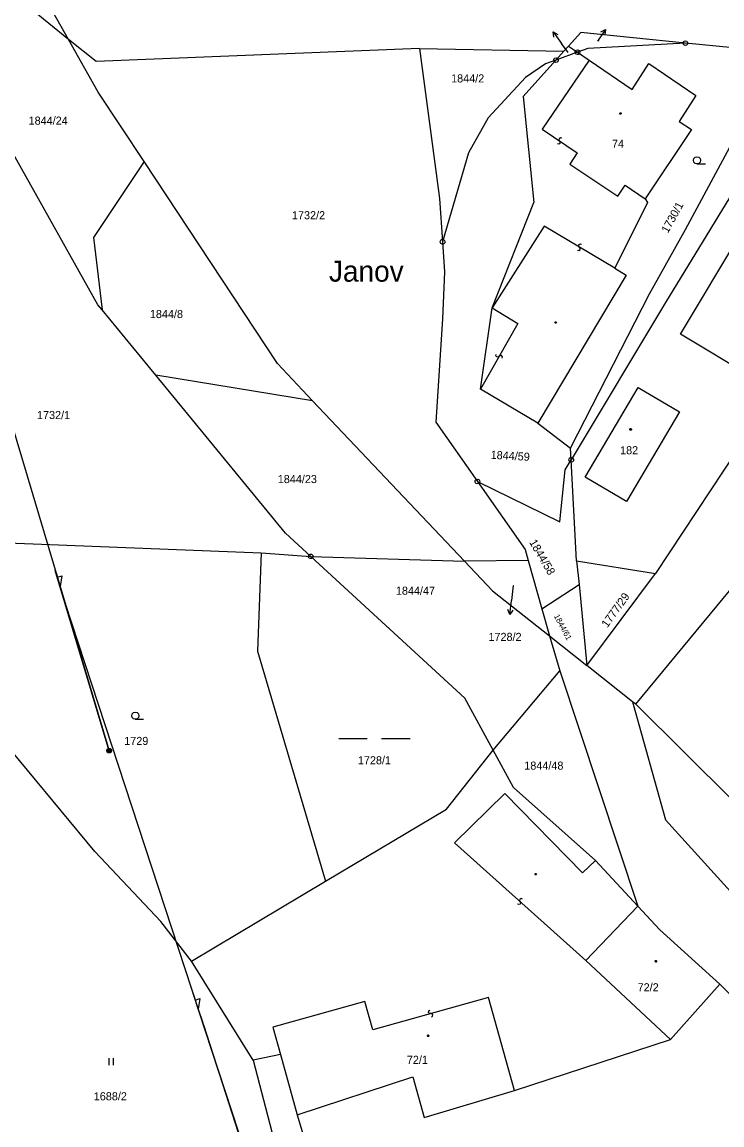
# Model space of a CAD drawing. Extents: x -747792 to -745414, y -1093712 to -1091463.
# Drawn here: x -747029.6 to -746956.1, y -1092274.2 to -1092158.4 of the extents above; entities that cross this region are included whole.
import ezdxf

# ---------------------------------------------------------------- set-up
doc = ezdxf.new("R2010")
doc.units = 0
for name, color, linetype in [('Pracovní_bod JDTM STC_VC', 7, 'Continuous'), ('Pracovní_bod JDTM STC_VC - výška', 7, 'Continuous'), ('Pracovní_bod JDTM STC_VC - číslo', 7, 'Continuous'), ('Pracovní_bod NN - výška', 7, 'Continuous'), ('Pracovní_bod polohopisu', 7, 'Continuous'), ('Pracovní_bod polohopisu - výška', 7, 'Continuous'), ('Pracovní_bod polohopisu - číslo', 7, 'Continuous'), ('Pracovní_bod VN - výška', 7, 'Continuous')]:
    doc.layers.add(name, color=color, linetype=linetype)

msp = doc.modelspace()

# ---------------------------------------------------------------- linework, layer by layer
at = {"layer": 'Pracovní_bod JDTM STC_VC - výška'}
for points in [[(-746966.77, -1092167.94), (-746966.72, -1092167.95), (-746966.7, -1092167.99), (-746966.69, -1092168.02), (-746966.7, -1092168.06), (-746966.74, -1092168.1), (-746966.77, -1092168.1), (-746966.82, -1092168.09), (-746966.84, -1092168.06), (-746966.85, -1092168.02), (-746966.84, -1092167.98), (-746966.8, -1092167.94)], [(-746973.52, -1092189.89), (-746973.47, -1092189.96), (-746973.52, -1092190.03), (-746973.6, -1092190.03), (-746973.65, -1092189.96), (-746973.6, -1092189.89)], [(-746965.68, -1092201.09), (-746965.63, -1092201.1), (-746965.6, -1092201.15), (-746965.59, -1092201.18), (-746965.6, -1092201.23), (-746965.65, -1092201.26), (-746965.68, -1092201.27), (-746965.73, -1092201.25), (-746965.76, -1092201.22), (-746965.77, -1092201.18), (-746965.76, -1092201.13), (-746965.72, -1092201.1)], [(-746975.6, -1092247.8), (-746975.56, -1092247.88), (-746975.6, -1092247.95), (-746975.7, -1092247.95), (-746975.74, -1092247.88), (-746975.7, -1092247.8)], [(-746963.05, -1092256.93), (-746963, -1092256.94), (-746962.98, -1092256.98), (-746962.97, -1092257.01), (-746962.98, -1092257.06), (-746963.02, -1092257.09), (-746963.05, -1092257.09), (-746963.09, -1092257.08), (-746963.12, -1092257.05), (-746963.14, -1092257.01), (-746963.12, -1092256.96), (-746963.08, -1092256.93)], [(-746986.95, -1092264.75), (-746986.9, -1092264.76), (-746986.88, -1092264.8), (-746986.86, -1092264.83), (-746986.88, -1092264.88), (-746986.92, -1092264.91), (-746986.95, -1092264.92), (-746986.99, -1092264.9), (-746987.02, -1092264.87), (-746987.03, -1092264.83), (-746987.02, -1092264.79), (-746986.98, -1092264.75)]]:
    msp.add_lwpolyline(points, close=True, dxfattribs=at)
at = {"layer": 'Pracovní_bod JDTM STC_VC - číslo'}
for points in [[(-746958.73, -1092173.31), (-746958.92, -1092173.26), (-746959.05, -1092173.12), (-746959.1, -1092172.94), (-746959.05, -1092172.75), (-746958.92, -1092172.61), (-746958.73, -1092172.56), (-746958.54, -1092172.61), (-746958.41, -1092172.75), (-746958.35, -1092172.94), (-746958.41, -1092173.12), (-746958.54, -1092173.26), (-746958.73, -1092173.31), (-746957.85, -1092173.31)], [(-747017.7, -1092231.61), (-747017.89, -1092231.56), (-747018.02, -1092231.42), (-747018.08, -1092231.24), (-747018.02, -1092231.05), (-747017.89, -1092230.91), (-747017.7, -1092230.86), (-747017.51, -1092230.91), (-747017.38, -1092231.05), (-747017.33, -1092231.24), (-747017.38, -1092231.42), (-747017.51, -1092231.56), (-747017.7, -1092231.61), (-747016.83, -1092231.61)], [(-746996.34, -1092233.64), (-746993.34, -1092233.64)], [(-746991.84, -1092233.64), (-746988.84, -1092233.64)], [(-747020.49, -1092267.17), (-747020.49, -1092267.92)], [(-747019.99, -1092267.92), (-747019.99, -1092267.17)]]:
    msp.add_lwpolyline(points, dxfattribs=at)
at = {"layer": 'Pracovní_bod NN - výška'}
for points in [[(-747024.71, -1092160.27), (-747034.1, -1092143.66)], [(-747024.71, -1092160.27), (-747037.12, -1092150.15)], [(-746970.91, -1092159.54), (-746972.2, -1092160.96)], [(-746959.95, -1092160.64), (-746970.91, -1092159.54)], [(-747021.59, -1092165.8), (-747024.71, -1092160.27)], [(-747021.82, -1092162.57), (-747024.71, -1092160.27)], [(-746945.49, -1092160), (-746948.23, -1092165.29), (-746962.05, -1092187.86), (-746971.93, -1092204.37)], [(-746959.95, -1092160.64), (-746970.19, -1092161.2)], [(-746949.91, -1092161.64), (-746959.95, -1092160.64)], [(-746987.85, -1092161.22), (-747021.82, -1092162.57)], [(-746987.85, -1092161.22), (-746985.75, -1092176.94)], [(-746987.85, -1092161.22), (-746972.69, -1092161.5)], [(-746973.53, -1092162.43), (-746972.69, -1092161.5)], [(-746971.28, -1092161.6), (-746973.53, -1092162.43)], [(-746972.2, -1092160.96), (-746972.69, -1092161.5)], [(-746972.2, -1092160.96), (-746971.28, -1092161.6)], [(-746970.19, -1092161.2), (-746971.28, -1092161.6)], [(-746971.28, -1092161.6), (-746970.06, -1092162.44)], [(-746959.95, -1092180.22), (-746949.91, -1092161.64)], [(-747021.62, -1092188.1), (-747035.75, -1092163)], [(-746976.98, -1092166.24), (-746973.53, -1092162.43)], [(-746974.63, -1092162.83), (-746976.74, -1092164.24)], [(-746973.53, -1092162.43), (-746974.63, -1092162.83)], [(-746970.06, -1092162.44), (-746965.52, -1092165.5)], [(-746965.52, -1092165.5), (-746963.79, -1092162.77)], [(-746963.79, -1092162.77), (-746958.85, -1092166.14)], [(-746976.74, -1092164.24), (-746980.64, -1092168.47)], [(-747016.78, -1092173.07), (-747021.59, -1092165.8)], [(-746976.98, -1092166.24), (-746975.87, -1092177.38)], [(-746958.85, -1092166.14), (-746960.61, -1092168.85)], [(-746980.64, -1092168.47), (-746982.72, -1092172.16)], [(-746959.32, -1092169.69), (-746964.15, -1092176.99)], [(-746960.61, -1092168.85), (-746959.32, -1092169.69)], [(-746982.72, -1092172.16), (-746985.44, -1092181.49)], [(-747016.78, -1092173.07), (-747022.1, -1092181.03)], [(-747002.78, -1092194.26), (-747016.78, -1092173.07)], [(-746985.75, -1092176.94), (-746985.44, -1092181.49)], [(-746980.24, -1092188.43), (-746975.87, -1092177.38)], [(-746963.93, -1092177.37), (-746967.35, -1092184.27)], [(-746964.15, -1092176.99), (-746963.93, -1092177.37)], [(-746963.7, -1092186.96), (-746959.95, -1092180.22)], [(-747022.1, -1092181.03), (-747021.19, -1092188.62)], [(-746985.44, -1092181.49), (-746985.23, -1092184.63)], [(-746960.47, -1092191.19), (-746954.11, -1092180.64)], [(-746985.23, -1092184.63), (-746985.44, -1092189.59)], [(-746966.15, -1092184.99), (-746975.42, -1092200.54)], [(-746967.35, -1092184.27), (-746966.15, -1092184.99)], [(-746971.99, -1092203.15), (-746963.7, -1092186.96)], [(-747021.19, -1092188.62), (-747021.62, -1092188.1)], [(-746981.44, -1092196.97), (-746980.24, -1092188.43)], [(-747015.55, -1092195.49), (-747021.19, -1092188.62)], [(-746985.44, -1092189.59), (-746986.15, -1092200.44)], [(-746952.49, -1092195.99), (-746960.47, -1092191.19)], [(-747002.78, -1092194.26), (-746999.08, -1092198.17)], [(-746999.08, -1092198.17), (-747015.55, -1092195.49)], [(-747001.92, -1092212.08), (-747015.55, -1092195.49)], [(-746975.42, -1092200.54), (-746981.44, -1092196.97)], [(-746970.46, -1092206.2), (-746964.91, -1092196.78)], [(-746964.91, -1092196.78), (-746960.58, -1092199.33)], [(-746950.17, -1092196.79), (-746963.07, -1092216.32)], [(-746999.08, -1092198.17), (-746983.14, -1092215.01)], [(-746960.58, -1092199.33), (-746966.13, -1092208.74)], [(-746986.15, -1092200.44), (-746981.78, -1092206.66)], [(-746975.42, -1092200.54), (-746971.99, -1092203.15)], [(-746971.93, -1092204.37), (-746971.99, -1092203.15)], [(-746972.56, -1092205.43), (-746971.93, -1092204.37)], [(-746971.36, -1092214.98), (-746971.93, -1092204.37)], [(-746965.16, -1092230.04), (-746943.99, -1092204.43)], [(-746973.12, -1092210.88), (-746972.56, -1092205.43)], [(-746981.78, -1092206.66), (-746973.12, -1092210.88)], [(-746981.78, -1092206.66), (-746976.77, -1092213.78)], [(-746966.13, -1092208.74), (-746970.46, -1092206.2)], [(-746999.28, -1092214.51), (-747001.92, -1092212.08)], [(-747037.36, -1092212.86), (-747004.48, -1092214.14)], [(-746976.77, -1092213.78), (-746976.44, -1092214.96)], [(-747004.48, -1092214.14), (-747004.88, -1092224.46)], [(-747004.48, -1092214.14), (-746999.28, -1092214.51)], [(-746999.28, -1092214.51), (-746983.14, -1092215.01)], [(-746983.11, -1092229.41), (-746999.28, -1092214.51)], [(-746976.44, -1092214.96), (-746983.14, -1092215.01)], [(-746983.14, -1092215.01), (-746980.19, -1092218.13)], [(-746976.44, -1092214.96), (-746975.01, -1092220.01)], [(-746971.36, -1092214.98), (-746963.07, -1092216.32)], [(-746971.36, -1092214.98), (-746971.11, -1092217.47)], [(-746970.28, -1092225.96), (-746963.07, -1092216.32)], [(-746980.19, -1092218.13), (-746974.21, -1092222.85)], [(-746975.01, -1092220.01), (-746971.11, -1092217.47)], [(-746971.11, -1092217.47), (-746970.28, -1092225.96)], [(-746975.01, -1092220.01), (-746974.21, -1092222.85)], [(-746974.21, -1092222.85), (-746973.13, -1092226.53)], [(-746974.21, -1092222.85), (-746970.28, -1092225.96)], [(-747004.88, -1092224.46), (-746997.74, -1092248.62)], [(-746980.14, -1092234.86), (-746973.13, -1092226.53)], [(-746973.13, -1092226.53), (-746964.93, -1092251.23)], [(-746965.49, -1092229.78), (-746970.28, -1092225.96)], [(-746980.14, -1092234.86), (-746983.11, -1092229.41)], [(-746965.49, -1092229.78), (-746962.04, -1092242.15)], [(-746965.16, -1092230.04), (-746965.49, -1092229.78)], [(-746965.16, -1092230.04), (-746949.9, -1092245.17)], [(-747021.96, -1092245.5), (-747032.59, -1092232.68)], [(-746985.01, -1092241.04), (-746980.14, -1092234.86)], [(-746978, -1092238.79), (-746980.14, -1092234.86)], [(-746969.39, -1092246.43), (-746978, -1092238.79)], [(-746997.74, -1092248.62), (-746985.01, -1092241.04)], [(-746962.04, -1092242.15), (-746946.7, -1092259.07)], [(-747015.01, -1092252.84), (-747021.96, -1092245.5)], [(-746964.93, -1092251.23), (-746969.39, -1092246.43)], [(-747011.8, -1092257), (-746997.74, -1092248.62)], [(-746964.93, -1092251.23), (-746970.4, -1092256.92)], [(-746962.62, -1092253.72), (-746964.93, -1092251.23)], [(-747011.8, -1092257), (-747015.01, -1092252.84)], [(-746956.34, -1092259.41), (-746962.62, -1092253.72)], [(-747005.34, -1092267.41), (-747011.8, -1092257)], [(-746961.51, -1092265.24), (-746970.4, -1092256.92)], [(-746956.34, -1092259.41), (-746961.51, -1092265.24)], [(-746953.13, -1092262.55), (-746956.34, -1092259.41)], [(-746977.89, -1092270.57), (-746961.51, -1092265.24)], [(-747002.47, -1092266.8), (-747005.34, -1092267.41)], [(-747002.47, -1092266.8), (-747000.7, -1092273.13)], [(-747005.34, -1092267.41), (-746997.05, -1092299.1)], [(-747000.7, -1092273.13), (-746988.57, -1092269.16)], [(-746988.57, -1092269.16), (-746987.38, -1092273.42)], [(-746987.38, -1092273.42), (-746977.89, -1092270.57)], [(-747000.7, -1092273.13), (-746993.42, -1092297.55)]]:
    msp.add_lwpolyline(points, dxfattribs=at)
at = {"layer": 'Pracovní_bod polohopisu'}
for points in [[(-746970.06, -1092162.44), (-746974.98, -1092169.66)], [(-746974.98, -1092169.66), (-746971.32, -1092172.17)], [(-746972.92, -1092170.62), (-746973.07, -1092170.58), (-746973.21, -1092170.67), (-746973.23, -1092170.82), (-746973.08, -1092171.03), (-746973.11, -1092171.18), (-746973.24, -1092171.26), (-746973.38, -1092171.21)], [(-746971.32, -1092172.17), (-746972.09, -1092173.33)], [(-746972.09, -1092173.33), (-746967.04, -1092176.7)], [(-746967.04, -1092176.7), (-746966.26, -1092175.55)], [(-746966.26, -1092175.55), (-746964.15, -1092176.99)], [(-746974.78, -1092179.85), (-746980.24, -1092188.43)], [(-746967.35, -1092184.27), (-746974.78, -1092179.85)], [(-746971.28, -1092182.37), (-746971.12, -1092182.4), (-746970.99, -1092182.3), (-746970.98, -1092182.15), (-746971.15, -1092181.95), (-746971.13, -1092181.8), (-746970.99, -1092181.71), (-746970.85, -1092181.75)], [(-746980.24, -1092188.43), (-746977.54, -1092190.06)], [(-746977.54, -1092190.06), (-746981.44, -1092196.97)], [(-746979.18, -1092193.72), (-746979.15, -1092193.57), (-746979.25, -1092193.44), (-746979.4, -1092193.43), (-746979.59, -1092193.6), (-746979.75, -1092193.58), (-746979.84, -1092193.45), (-746979.8, -1092193.31)], [(-746984.19, -1092244.57), (-746978.89, -1092239.39)], [(-746978.89, -1092239.39), (-746970.73, -1092247.74)], [(-746984.19, -1092244.57), (-746970.4, -1092256.92)], [(-746970.73, -1092247.74), (-746969.39, -1092246.43)], [(-746977.03, -1092250.48), (-746977.17, -1092250.42), (-746977.32, -1092250.49), (-746977.36, -1092250.64), (-746977.24, -1092250.87), (-746977.28, -1092251.01), (-746977.43, -1092251.07), (-746977.56, -1092251.01)], [(-746993.61, -1092261.22), (-747003.27, -1092263.92)], [(-746992.77, -1092264.21), (-746993.61, -1092261.22)], [(-746980.61, -1092260.81), (-746992.77, -1092264.21)], [(-746977.89, -1092270.57), (-746980.61, -1092260.81)], [(-746986.61, -1092262.88), (-746986.48, -1092262.79), (-746986.47, -1092262.62), (-746986.57, -1092262.51), (-746986.82, -1092262.5), (-746986.92, -1092262.38), (-746986.89, -1092262.22), (-746986.77, -1092262.14)], [(-747003.27, -1092263.92), (-747002.47, -1092266.8)]]:
    msp.add_lwpolyline(points, dxfattribs=at)
at = {"layer": 'Pracovní_bod polohopisu - výška'}
for points in [[(-746973.83, -1092159.46), (-746972.94, -1092160.67)], [(-746973.74, -1092160.01), (-746973.83, -1092159.46), (-746973.33, -1092159.72)], [(-746968.34, -1092159.2), (-746969.18, -1092160.44)], [(-746968.83, -1092159.47), (-746968.34, -1092159.2), (-746968.41, -1092159.75)], [(-746972.24, -1092161.62), (-746972.94, -1092160.67)], [(-746978.01, -1092217.57), (-746978.2, -1092219.13)], [(-746978.38, -1092220.62), (-746978.2, -1092219.13)], [(-746978.07, -1092220.15), (-746978.38, -1092220.62), (-746978.57, -1092220.09)]]:
    msp.add_lwpolyline(points, dxfattribs=at)
at = {"layer": 'Pracovní_bod polohopisu - číslo'}
for points in [[(-747030.74, -1092200.43), (-747020.45, -1092234.91), (-747026.1, -1092215.99)], [(-747026.02, -1092216.23), (-747025.88, -1092216.71), (-747025.4, -1092216.57), (-747025.59, -1092217.67), (-747025.17, -1092219.11)], [(-747025.09, -1092219.35), (-746997.09, -1092304.73), (-747011.64, -1092260.38)], [(-747020.52, -1092234.67), (-747020.37, -1092234.67), (-747020.24, -1092234.76), (-747020.2, -1092234.9), (-747020.24, -1092235.05), (-747020.37, -1092235.14), (-747020.52, -1092235.14), (-747020.65, -1092235.05), (-747020.7, -1092234.9), (-747020.65, -1092234.76), (-747020.52, -1092234.67), (-747020.51, -1092234.69), (-747020.39, -1092234.69), (-747020.31, -1092234.73), (-747020.59, -1092234.73), (-747020.63, -1092234.77), (-747020.27, -1092234.77), (-747020.27, -1092234.81), (-747020.63, -1092234.81), (-747020.65, -1092234.85), (-747020.25, -1092234.85), (-747020.23, -1092234.89), (-747020.67, -1092234.89), (-747020.67, -1092234.93), (-747020.23, -1092234.93), (-747020.24, -1092234.97), (-747020.65, -1092234.97), (-747020.65, -1092235.01), (-747020.24, -1092235.01), (-747020.26, -1092235.05), (-747020.62, -1092235.05), (-747020.58, -1092235.09), (-747020.3, -1092235.09), (-747020.36, -1092235.13), (-747020.53, -1092235.13)], [(-747011.56, -1092260.61), (-747011.4, -1092261.09), (-747010.93, -1092260.93), (-747011.09, -1092262.04), (-747010.62, -1092263.46)], [(-747010.55, -1092263.7), (-746977.75, -1092365.49), (-746994.69, -1092312.93)]]:
    msp.add_lwpolyline(points, dxfattribs=at)
at = {"layer": 'Pracovní_bod VN - výška'}
for points in [[(-746960.08, -1092160.42), (-746959.92, -1092160.39), (-746959.78, -1092160.45), (-746959.71, -1092160.59), (-746959.72, -1092160.75), (-746959.82, -1092160.86), (-746959.98, -1092160.89), (-746960.12, -1092160.83), (-746960.19, -1092160.69), (-746960.18, -1092160.53)], [(-746971.41, -1092161.38), (-746971.25, -1092161.35), (-746971.11, -1092161.41), (-746971.04, -1092161.55), (-746971.05, -1092161.71), (-746971.15, -1092161.82), (-746971.31, -1092161.85), (-746971.45, -1092161.79), (-746971.52, -1092161.65), (-746971.51, -1092161.49)], [(-746973.66, -1092162.21), (-746973.5, -1092162.18), (-746973.36, -1092162.24), (-746973.29, -1092162.38), (-746973.3, -1092162.54), (-746973.4, -1092162.65), (-746973.56, -1092162.68), (-746973.7, -1092162.62), (-746973.77, -1092162.48), (-746973.76, -1092162.32)], [(-746985.57, -1092181.27), (-746985.41, -1092181.24), (-746985.27, -1092181.3), (-746985.2, -1092181.44), (-746985.21, -1092181.6), (-746985.31, -1092181.71), (-746985.47, -1092181.74), (-746985.61, -1092181.68), (-746985.68, -1092181.54), (-746985.67, -1092181.38)], [(-746972.06, -1092204.15), (-746971.9, -1092204.12), (-746971.76, -1092204.18), (-746971.69, -1092204.32), (-746971.7, -1092204.48), (-746971.8, -1092204.59), (-746971.96, -1092204.62), (-746972.1, -1092204.56), (-746972.17, -1092204.42), (-746972.16, -1092204.26)], [(-746981.91, -1092206.44), (-746981.75, -1092206.41), (-746981.61, -1092206.47), (-746981.54, -1092206.61), (-746981.55, -1092206.77), (-746981.65, -1092206.88), (-746981.81, -1092206.91), (-746981.95, -1092206.85), (-746982.02, -1092206.71), (-746982.01, -1092206.55)], [(-746999.21, -1092214.27), (-746999.08, -1092214.36), (-746999.03, -1092214.51), (-746999.08, -1092214.66), (-746999.21, -1092214.75), (-746999.35, -1092214.75), (-746999.48, -1092214.66), (-746999.53, -1092214.51), (-746999.48, -1092214.36), (-746999.35, -1092214.27)]]:
    msp.add_lwpolyline(points, close=True, dxfattribs=at)
for points in [[(-746959.97, -1092160.66), (-746959.93, -1092160.62)], [(-746971.3, -1092161.62), (-746971.26, -1092161.58)], [(-746973.55, -1092162.45), (-746973.51, -1092162.41)], [(-746985.46, -1092181.51), (-746985.42, -1092181.47)], [(-746971.95, -1092204.39), (-746971.91, -1092204.35)], [(-746981.8, -1092206.68), (-746981.76, -1092206.64)], [(-746999.31, -1092214.51), (-746999.26, -1092214.51)]]:
    msp.add_lwpolyline(points, dxfattribs=at)

# ---------------------------------------------------------------- texts
at = {"layer": 'Pracovní_bod JDTM STC_VC'}
for s, height, p in [('1730/2', 0.05, (-746969.18, -1092160.44)), ('1905', 0.05, (-746972.24, -1092161.62)), ('1844/2', 0.85, (-746984.54, -1092164.77)), ('1844/24', 0.85, (-747028.9, -1092169.2)), ('74', 0.85, (-746967.65, -1092171.63)), ('1732/2', 0.85, (-747001.25, -1092179.13)), ('1844/8', 0.85, (-747016.17, -1092189.5)), ('1732/1', 0.85, (-747028.02, -1092200.1)), ('182', 0.85, (-746966.8, -1092203.8)), ('1844/23', 0.85, (-747002.74, -1092206.82)), ('1844/47', 0.85, (-746990.34, -1092218.54)), ('1728/2', 0.05, (-746978.12, -1092217.57)), ('1729', 0.85, (-747018.86, -1092234.31)), ('1728/1', 0.85, (-746994.33, -1092236.34)), ('1844/48', 0.85, (-746976.86, -1092236.9)), ('72/2', 0.85, (-746964.96, -1092260.17)), ('72/1', 0.85, (-746989.19, -1092267.78)), ('1688/2', 0.85, (-747022.06, -1092271.61))]:
    msp.add_text(s, height=height, dxfattribs=at).set_placement(p)
for s, height, rotation, p in [('1730/1', 0.85, 61.1919, (-746961.78, -1092180.65)), ('1844/59', 0.85, 356.7235, (-746980.41, -1092204.26)), ('1844/58', 0.85, 300.4018, (-746976.37, -1092213.03)), ('1777/29', 0.85, 54.3737, (-746968.14, -1092222.06)), ('1844/61', 0.61, 298.2245, (-746973.77, -1092220.78))]:
    msp.add_text(s, height=height, rotation=rotation, dxfattribs=at).set_placement(p)
at = {"layer": 'Pracovní_bod polohopisu - výška'}
for s, height, p in [('Janov', 2.2, (-746997.37, -1092185.68)), ('1728/2', 0.85, (-746980.62, -1092223.39))]:
    msp.add_text(s, height=height, dxfattribs=at).set_placement(p)

doc.saveas('drawing.dxf')
